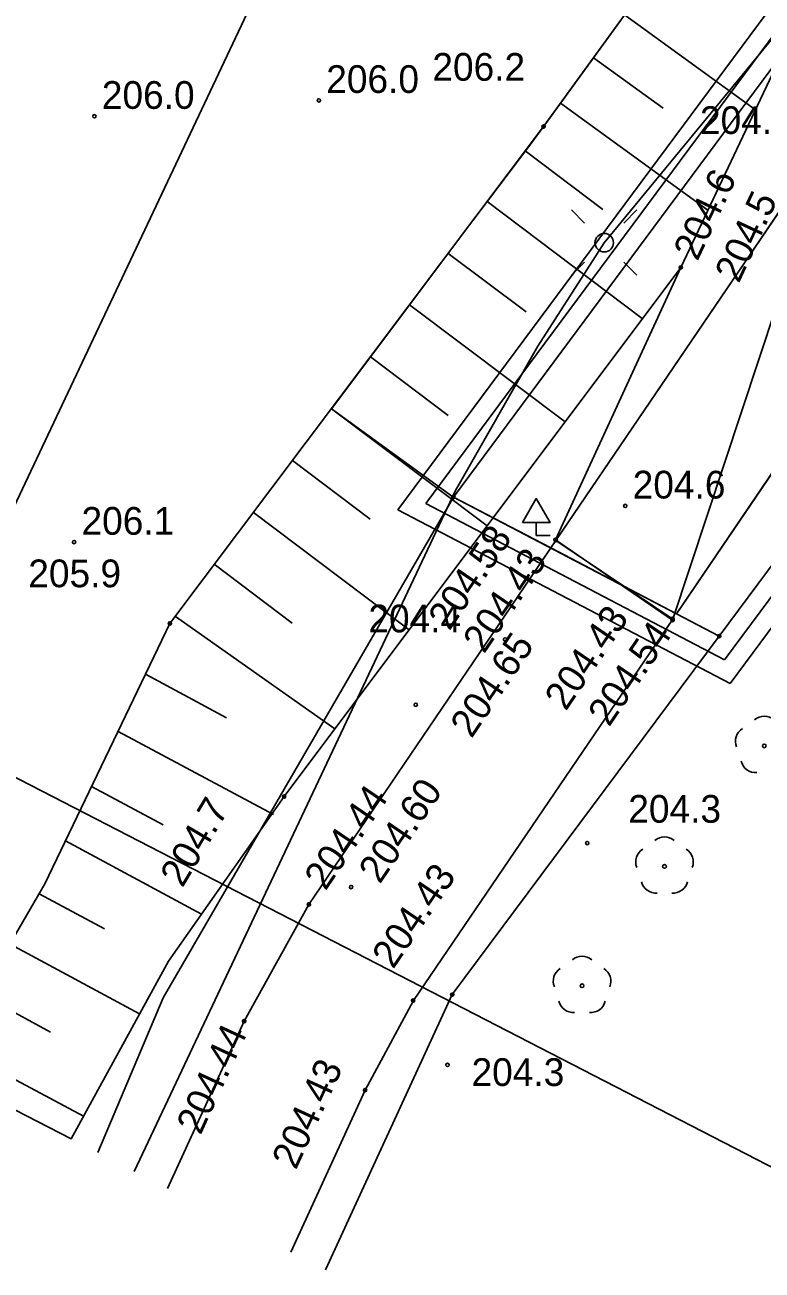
# Model space of a CAD drawing. Extents: x 6512606 to 6513006, y 6022524 to 6022728.
# Drawn here: x 6512694.69 to 6512714.63, y 6022553.25 to 6022586.93 of the extents above; entities that cross this region are included whole.
import ezdxf

# ---------------------------------------------------------------- set-up
doc = ezdxf.new("R2010")
doc.units = 0
for name, color, linetype in [('000 Inne (niezydentyfikowane)', 7, 'Continuous'), ('203-punkt graniczny', 7, 'Continuous'), ('217-kontur klasyfikacyjny', 7, 'Continuous'), ('218-kontur użytku gruntowego', 7, 'Continuous'), ('219-działka ewidencyjna', 7, 'Continuous'), ('4', 7, 'Continuous'), ('407-Znak drogowy', 7, 'Continuous'), ('Default', 7, 'Continuous'), ('drzewo liściaste', 7, 'Continuous'), ('drzewo liściaste (punkt)', 7, 'Continuous'), ('jezdnia', 7, 'Continuous'), ('jezdnia (powierzchnia)', 7, 'Continuous'), ('kolor_kostka_bet', 7, 'Continuous'), ('kolor_sc_rowerowa', 7, 'Continuous'), ('krawężnik (linia)', 7, 'Continuous'), ('latarnia', 7, 'Continuous'), ('maxp_kan_deszczowa', 7, 'Continuous'), ('maxp_kraw_nawierzchni', 7, 'Continuous'), ('maxp_obrzeże', 7, 'Continuous'), ('maxp_ramka_2', 7, 'Continuous'), ('Obszar opracowania', 7, 'Continuous'), ('pikieta naturalna', 7, 'Continuous'), ('pikieta naturalna-Atr2', 7, 'Continuous'), ('pikieta sztuczna', 7, 'Continuous'), ('pikieta sztuczna-Atr2', 7, 'Continuous'), ('przewód elektroenergetyczny (linia)', 7, 'Continuous'), ('punkt wysokościowy naturalny', 7, 'Continuous'), ('punkt wysokościowy naturalny-Atr2', 7, 'Continuous'), ('punkt wysokościowy sztuczny', 7, 'Continuous'), ('punkt wysokościowy sztuczny-Atr2', 7, 'Continuous'), ('skarpa nieumocniona', 7, 'Continuous')]:
    doc.layers.add(name, color=color, linetype=linetype)

# ---------------------------------------------------------------- blocks, each defined once
blk = doc.blocks.new('203')
at = {"layer": 'Default'}
blk.add_circle((0, 0), 0.45, dxfattribs=at)
blk = doc.blocks.new('PW01')
at = {"layer": 'Default'}
blk.add_circle((0, 0), 0.45, dxfattribs=at)
blk = doc.blocks.new('PW02')
at = {"layer": 'Default'}
blk.add_circle((0, 0), 0.45, dxfattribs=at)
blk = doc.blocks.new('OP021')
at = {"layer": 'Default'}
blk.add_circle((0, 0), 0.5, dxfattribs=at)
for centre, start, end in [((0, 4), 49.272, 130.728), ((-3.8, 1.24), 121.308, 202.548), ((3.8, 1.24), 337.452, 58.692), ((-2.35, -3.24), 193.221, 274.871), ((2.35, -3.24), 265.129, 346.779)]:
    blk.add_arc(centre, 4, start, end, dxfattribs=at)
blk = doc.blocks.new('407')
at = {"layer": 'Default'}
for p, q in [((0, 3.5), (0, 0)), ((0, 0), (3.75, 0))]:
    blk.add_line(p, q, dxfattribs=at)
blk.add_lwpolyline([(-3.75, 3.5), (0, 10), (3.75, 3.5)], close=True, dxfattribs=at)
blk = doc.blocks.new('SM01')
at = {"layer": 'Default'}
for p, q in [((-5.3, 5.31), (-8.83, 8.84)), ((5.31, 5.31), (8.84, 8.84)), ((-5.3, -5.3), (-8.83, -8.83)), ((5.31, -5.3), (8.84, -8.83))]:
    blk.add_line(p, q, dxfattribs=at)
blk.add_circle((0, 0), 2.5, dxfattribs=at)

msp = doc.modelspace()

# ---------------------------------------------------------------- linework, layer by layer
at = {"layer": '000 Inne (niezydentyfikowane)'}
for p, q in [((6512710.91, 6022587.2), (6512714.45, 6022584.63)), ((6512710.07, 6022586.04), (6512711.95, 6022584.68)), ((6512709.18, 6022584.81), (6512713.16, 6022581.92)), ((6512708.22, 6022583.52), (6512710.32, 6022581.94)), ((6512707.19, 6022582.15), (6512711.39, 6022578.99)), ((6512706.14, 6022580.75), (6512708.25, 6022579.17)), ((6512705.09, 6022579.36), (6512709.3, 6022576.19)), ((6512704.04, 6022577.95), (6512706.14, 6022576.37)), ((6512702.98, 6022576.55), (6512707.19, 6022573.38)), ((6512701.93, 6022575.15), (6512704.03, 6022573.56)), ((6512700.87, 6022573.74), (6512705.08, 6022570.57)), ((6512699.81, 6022572.34), (6512701.92, 6022570.75)), ((6512698.76, 6022570.93), (6512703.07, 6022567.89)), ((6512697.95, 6022569.37), (6512700.14, 6022568.19)), ((6512697.21, 6022567.82), (6512701.41, 6022565.57)), ((6512696.49, 6022566.33), (6512698.43, 6022565.29)), ((6512695.79, 6022564.86), (6512699.47, 6022562.88)), ((6512695.07, 6022563.43), (6512696.84, 6022562.48)), ((6512694.29, 6022562.07), (6512697.79, 6022560.18)), ((6512693.49, 6022560.71), (6512695.38, 6022559.69)), ((6512692.69, 6022559.33), (6512696.27, 6022557.41))]:
    msp.add_line(p, q, dxfattribs=at)
at = {"layer": '217-kontur klasyfikacyjny'}
for points in [[(6512706.28, 6022574.16), (6512716.29, 6022587.65)], [(6512723.14, 6022583.41), (6512713.47, 6022570.4)], [(6512698.43, 6022560.61), (6512706.28, 6022574.16)], [(6512713.47, 6022570.4), (6512706.25, 6022560.7)], [(6512696.659, 6022556.427), (6512698.43, 6022560.61)], [(6512706.25, 6022560.7), (6512702.816, 6022553.255)]]:
    msp.add_lwpolyline(points, dxfattribs=at)
at = {"layer": '218-kontur użytku gruntowego'}
for points in [[(6512716.29, 6022587.65), (6512706.28, 6022574.16)], [(6512706.28, 6022574.16), (6512716.29, 6022587.65)], [(6512713.47, 6022570.4), (6512723.14, 6022583.41)], [(6512723.14, 6022583.41), (6512713.47, 6022570.4)], [(6512706.28, 6022574.16), (6512698.43, 6022560.61)], [(6512698.43, 6022560.61), (6512706.28, 6022574.16)], [(6512706.28, 6022574.16), (6512713.47, 6022570.4)], [(6512713.47, 6022570.4), (6512706.28, 6022574.16)], [(6512706.25, 6022560.7), (6512713.47, 6022570.4)], [(6512713.47, 6022570.4), (6512706.25, 6022560.7)], [(6512698.43, 6022560.61), (6512696.659, 6022556.427)], [(6512696.659, 6022556.427), (6512698.43, 6022560.61)], [(6512702.816, 6022553.255), (6512706.25, 6022560.7)], [(6512706.25, 6022560.7), (6512702.816, 6022553.255)]]:
    msp.add_lwpolyline(points, dxfattribs=at)
at = {"layer": '219-działka ewidencyjna'}
for points in [[(6512706.28, 6022574.16), (6512716.29, 6022587.65)], [(6512723.14, 6022583.41), (6512713.47, 6022570.4)], [(6512706.28, 6022574.16), (6512713.47, 6022570.4)], [(6512706.25, 6022560.7), (6512713.47, 6022570.4)], [(6512706.25, 6022560.7), (6512702.816, 6022553.255)]]:
    msp.add_lwpolyline(points, dxfattribs=at)
at = {"layer": '4'}
for points in [[(6512706.28, 6022574.16), (6512716.29, 6022587.65)], [(6512723.14, 6022583.41), (6512713.47, 6022570.4)], [(6512706.28, 6022574.16), (6512713.47, 6022570.4)], [(6512706.25, 6022560.7), (6512713.47, 6022570.4)], [(6512706.25, 6022560.7), (6512702.816, 6022553.255)]]:
    msp.add_lwpolyline(points, dxfattribs=at)
at = {"layer": 'jezdnia'}
msp.add_lwpolyline([(6512731.08, 6022620.65), (6512728.82, 6022611.46), (6512722.83, 6022600.42), (6512717.94, 6022592.02), (6512712.43, 6022580.37), (6512709.04, 6022573), (6512712.21, 6022570.83), (6512715.01, 6022579.3), (6512720.33, 6022590.74), (6512725.35, 6022598.98), (6512731.85, 6022610.22), (6512735.75, 6022620.3)], close=True, dxfattribs=at)
at = {"layer": 'jezdnia (powierzchnia)'}
msp.add_lwpolyline([(6512701.878, 6022553.738), (6512703.89, 6022558.12), (6512705.2, 6022560.54), (6512712.22, 6022570.86), (6512709.05, 6022572.98), (6512702.37, 6022563.14), (6512700.62, 6022559.98), (6512698.544, 6022555.456)], dxfattribs=at)
at = {"layer": 'kolor_kostka_bet'}
msp.add_line((6512718.891, 6022580.693), (6512712.317, 6022571.003), dxfattribs=at)
for points in [[(6512708.915, 6022572.782), (6512706.28, 6022574.16), (6512716.29, 6022587.65), (6512727.91, 6022609.85), (6512731.23, 6022647.88), (6512731.197, 6022649.415), (6512729.023, 6022649.531)], [(6512729.023, 6022649.531), (6512731.197, 6022649.415), (6512731.23, 6022647.88), (6512727.91, 6022609.85), (6512716.29, 6022587.65), (6512706.28, 6022574.16), (6512708.915, 6022572.782)], [(6512712.317, 6022571.003), (6512713.47, 6022570.4), (6512723.14, 6022583.41)], [(6512712.317, 6022571.003), (6512713.47, 6022570.4), (6512723.14, 6022583.41)], [(6512708.915, 6022572.782), (6512710.182, 6022574.647), (6512714.169, 6022580.521), (6512715.209, 6022582.053)]]:
    msp.add_lwpolyline(points, dxfattribs=at)
at = {"layer": 'kolor_sc_rowerowa'}
msp.add_lwpolyline([(6512715.209, 6022582.053), (6512714.169, 6022580.521), (6512710.182, 6022574.647), (6512708.915, 6022572.782), (6512710.888, 6022571.75), (6512712.317, 6022571.003), (6512718.891, 6022580.693)], dxfattribs=at)
at = {"layer": 'krawężnik (linia)'}
msp.add_lwpolyline([(6512701.878, 6022553.738), (6512703.89, 6022558.12), (6512705.2, 6022560.54), (6512712.22, 6022570.86), (6512709.05, 6022572.98), (6512702.37, 6022563.14), (6512700.62, 6022559.98), (6512698.55, 6022555.453)], dxfattribs=at)
at = {"layer": 'maxp_kan_deszczowa'}
msp.add_lwpolyline([(6512710.95, 6022587.254), (6512708.754, 6022584.227), (6512708.344, 6022583.68), (6512707.509, 6022582.57), (6512706.808, 6022581.639), (6512702.981, 6022576.55), (6512706.26, 6022574.17), (6512712.317, 6022571.003), (6512714.661, 6022574.458), (6512716.376, 6022576.986), (6512720.208, 6022582.729), (6512721.429, 6022584.824), (6512726.855, 6022595.183)], dxfattribs=at)
at = {"layer": 'maxp_kraw_nawierzchni'}
msp.add_lwpolyline([(6512709.05, 6022572.98), (6512710.888, 6022571.75), (6512712.317, 6022571.003)], dxfattribs=at)
at = {"layer": 'maxp_obrzeże'}
for p, q in [((6512716.334, 6022583.71), (6512709.055, 6022572.987)), ((6512718.891, 6022580.693), (6512712.317, 6022571.003))]:
    msp.add_line(p, q, dxfattribs=at)
at = {"layer": 'maxp_ramka_2'}
for p, q in [((6512723.442, 6022582.139), (6512713.763, 6022569.118)), ((6512704.78, 6022573.816), (6512713.763, 6022569.118)), ((6512705.53, 6022573.988), (6512713.617, 6022569.759))]:
    msp.add_line(p, q, dxfattribs=at)
for points in [[(6512704.78, 6022573.816), (6512715.44, 6022588.183), (6512724.41, 6022605.32)], [(6512705.53, 6022573.988), (6512715.865, 6022587.917), (6512721.086, 6022597.89)], [(6512723.291, 6022582.775), (6512713.617, 6022569.759)]]:
    msp.add_lwpolyline(points, dxfattribs=at)
at = {"layer": 'Obszar opracowania'}
msp.add_lwpolyline([(6512710.98, 6022693.84), (6512748.35, 6022694.16), (6512798.11, 6022695.25), (6512807.47, 6022695.46), (6512809.66, 6022606.87), (6512863.71, 6022622.03), (6512875.13, 6022581.36), (6512755.22, 6022535.25), (6512691.61, 6022568.03), (6512709.16, 6022605.16)], close=True, dxfattribs=at)
at = {"layer": 'przewód elektroenergetyczny (linia)'}
msp.add_lwpolyline([(6512726.13, 6022606.96), (6512716.02, 6022587.92), (6512710.36, 6022581.04), (6512708.56, 6022578.24), (6512706.34, 6022574.34), (6512697.643, 6022555.92)], dxfattribs=at)
at = {"layer": 'skarpa nieumocniona'}
msp.add_lwpolyline([(6512728.82, 6022611.46), (6512722.83, 6022600.42), (6512717.94, 6022592.02), (6512712.43, 6022580.37), (6512701.7, 6022566.06), (6512698.57, 6022561.61), (6512695.94, 6022556.8), (6512692.31, 6022558.67), (6512695.23, 6022563.7), (6512698.61, 6022570.74), (6512708.72, 6022584.18), (6512714.93, 6022592.74), (6512720.42, 6022602.03), (6512725.72, 6022613.25), (6512727.1, 6022620.51), (6512731.08, 6022620.65)], close=True, dxfattribs=at)
msp.add_lwpolyline([(6512728.82, 6022611.46), (6512722.83, 6022600.42), (6512717.94, 6022592.02), (6512712.43, 6022580.37), (6512701.7, 6022566.06), (6512698.57, 6022561.61), (6512695.94, 6022556.8), (6512692.31, 6022558.67), (6512695.23, 6022563.7), (6512698.61, 6022570.74), (6512708.72, 6022584.18), (6512714.93, 6022592.74), (6512720.42, 6022602.03), (6512725.72, 6022613.25), (6512727.1, 6022620.51), (6512731.08, 6022620.65)], close=True, dxfattribs=at)

# ---------------------------------------------------------------- block references
at = {"layer": '203-punkt graniczny', "xscale": 0.1, "yscale": 0.10000000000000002}
for p in [(6512706.28, 6022574.16), (6512713.47, 6022570.4), (6512706.25, 6022560.7)]:
    msp.add_blockref('203', p, dxfattribs=at)
at = {"layer": '407-Znak drogowy', "xscale": 0.1, "yscale": 0.10000000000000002}
msp.add_blockref('407', (6512708.52, 6022573.12), dxfattribs=at)
at = {"layer": 'drzewo liściaste', "xscale": 0.1, "yscale": 0.10000000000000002}
for p in [(6512711.99, 6022564.17), (6512709.76, 6022560.94)]:
    msp.add_blockref('OP021', p, dxfattribs=at)
at = {"layer": 'drzewo liściaste (punkt)', "xscale": 0.1, "yscale": 0.10000000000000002}
msp.add_blockref('OP021', (6512714.69, 6022567.43), dxfattribs=at)
at = {"layer": 'latarnia', "xscale": 0.1, "yscale": 0.10000000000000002}
msp.add_blockref('SM01', (6512710.36, 6022581.04), dxfattribs=at)
at = {"layer": 'pikieta naturalna', "xscale": 0.1, "yscale": 0.10000000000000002}
for p in [(6512702.64, 6022584.89), (6512708.72, 6022584.18), (6512712.43, 6022580.37), (6512698.61, 6022570.74), (6512701.7, 6022566.06)]:
    msp.add_blockref('PW01', p, dxfattribs=at)
at = {"layer": 'pikieta sztuczna', "xscale": 0.1, "yscale": 0.10000000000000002}
for p in [(6512709.04, 6022573), (6512712.21, 6022570.83), (6512707.68, 6022570.31), (6512703.51, 6022563.61)]:
    msp.add_blockref('PW01', p, dxfattribs=at)
at = {"layer": 'punkt wysokościowy naturalny', "xscale": 0.1, "yscale": 0.10000000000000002}
for p in [(6512696.57, 6022584.46), (6512710.93, 6022573.92), (6512696.02, 6022572.94), (6512705.26, 6022568.54), (6512709.9, 6022564.8), (6512706.12, 6022558.8)]:
    msp.add_blockref('PW01', p, dxfattribs=at)
at = {"layer": 'punkt wysokościowy sztuczny', "xscale": 0.1, "yscale": 0.10000000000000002}
for p in [(6512709.05, 6022572.99), (6512712.21, 6022570.87), (6512702.37, 6022563.14), (6512705.19, 6022560.54), (6512700.62, 6022559.98), (6512703.89, 6022558.12)]:
    msp.add_blockref('PW02', p, dxfattribs=at)

# ---------------------------------------------------------------- texts
at = {"layer": 'pikieta naturalna-Atr2'}
for s, p in [('206.2', (6512705.71, 6022585.42)), ('206.0', (6512702.84, 6022585.09)), ('205.9', (6512694.78, 6022571.72))]:
    msp.add_text(s, height=0.75, dxfattribs=at).set_placement(p)
for s, rotation, p in [('204.6', 64.688, (6512712.88, 6022580.52)), ('204.5', 65.06, (6512714, 6022579.92)), ('204.7', 59.233, (6512698.95, 6022563.57))]:
    msp.add_text(s, height=0.75, rotation=rotation, dxfattribs=at).set_placement(p)
at = {"layer": 'pikieta sztuczna-Atr2'}
for s, rotation, p in [('204.58', 55.923, (6512706.17, 6022570.52)), ('204.54', 55.736, (6512710.49, 6022567.92)), ('204.65', 55.923, (6512706.77, 6022567.61)), ('204.60', 55.923, (6512704.29, 6022563.67))]:
    msp.add_text(s, height=0.75, rotation=rotation, dxfattribs=at).set_placement(p)
at = {"layer": 'punkt wysokościowy naturalny-Atr2'}
for s, p in [('206.0', (6512696.77, 6022584.66)), ('204.5', (6512712.95, 6022583.98)), ('204.6', (6512711.13, 6022574.12)), ('206.1', (6512696.22, 6022573.14)), ('204.4', (6512703.98, 6022570.5)), ('204.3', (6512711.01, 6022565.35)), ('204.3', (6512706.77, 6022558.23))]:
    msp.add_text(s, height=0.75, dxfattribs=at).set_placement(p)
at = {"layer": 'punkt wysokościowy sztuczny-Atr2'}
for s, rotation, p in [('204.43', 55.828, (6512707.11, 6022569.9)), ('204.43', 55.775, (6512709.32, 6022568.35)), ('204.44', 55.828, (6512702.82, 6022563.49)), ('204.43', 55.775, (6512704.65, 6022561.37)), ('204.44', 65.355, (6512699.44, 6022556.88)), ('204.43', 65.335, (6512702.02, 6022555.94))]:
    msp.add_text(s, height=0.75, rotation=rotation, dxfattribs=at).set_placement(p)

doc.saveas('drawing.dxf')
